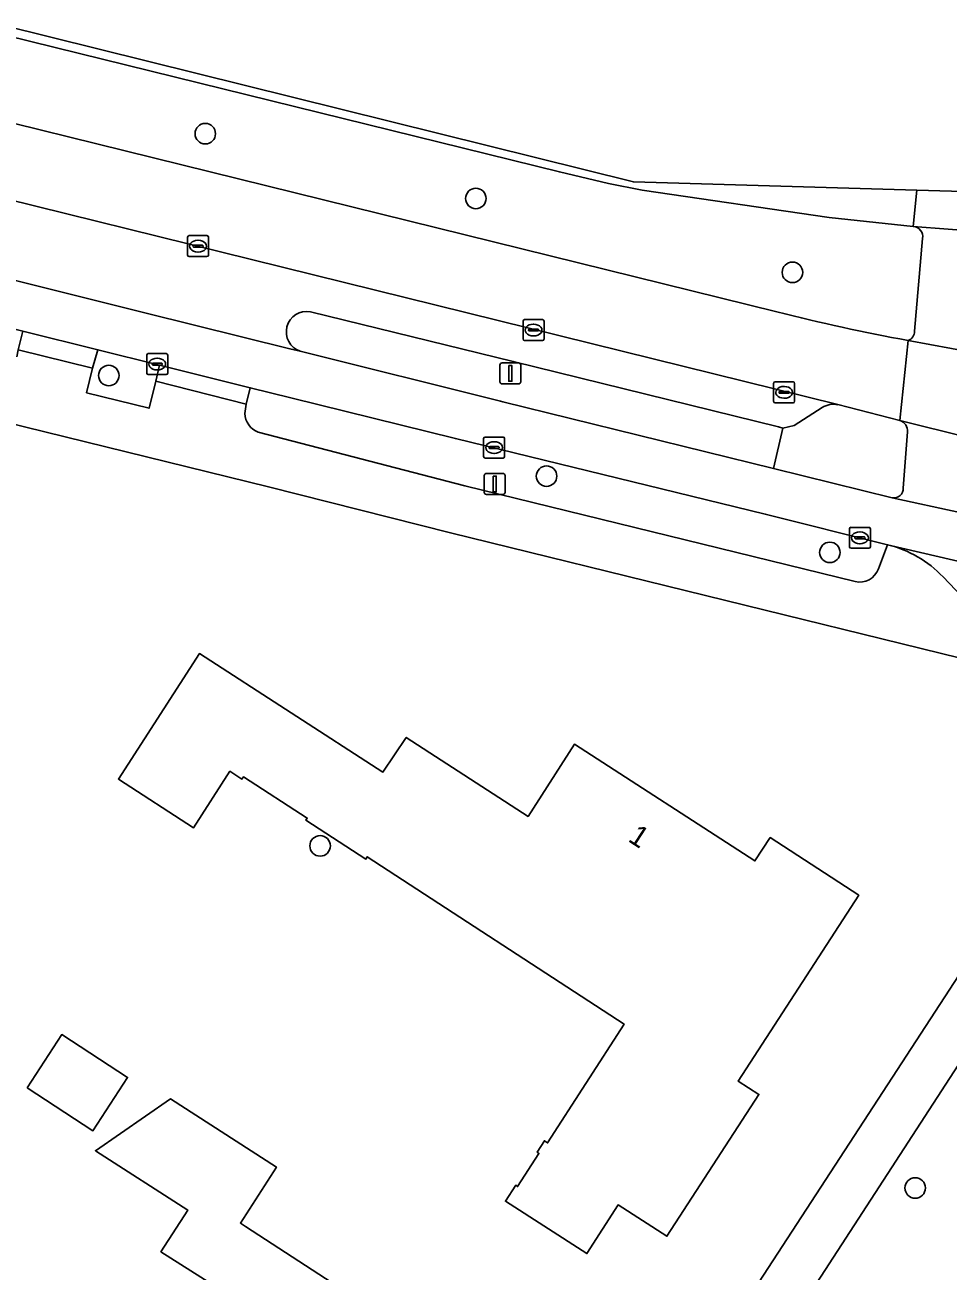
# Model space of a CAD drawing. Extents: x 161139 to 161601, y 381708 to 382245.
# Drawn here: x 161533 to 161577, y 382109.7 to 382169.1 of the extents above; entities that cross this region are included whole.
import ezdxf

# ---------------------------------------------------------------- set-up
doc = ezdxf.new("R2010")
doc.units = 0
for name, color, linetype in [('IMGEO_Berm_groen', 7, 'Continuous'), ('IMGEO_Boom', 7, 'Continuous'), ('IMGEO_Erf', 7, 'Continuous'), ('IMGEO_Fietspad_gesloten', 7, 'Continuous'), ('IMGEO_Groenvoorziening', 7, 'Continuous'), ('IMGEO_Kolk', 7, 'Continuous'), ('IMGEO_Lichtmast', 7, 'Continuous'), ('IMGEO_Pand', 7, 'Continuous'), ('IMGEO_Pand_nummerreeks', 7, 'Continuous'), ('IMGEO_Parkeervlak_open', 7, 'Continuous'), ('IMGEO_Rijbaan_lokaal_gesloten', 7, 'Continuous'), ('IMGEO_Voetpad_open', 7, 'Continuous')]:
    doc.layers.add(name, color=color, linetype=linetype)

msp = doc.modelspace()

# ---------------------------------------------------------------- linework, layer by layer
at = {"layer": 'IMGEO_Berm_groen'}
for points in [[(161500, 382176.547), (161460.894, 382186.197), (161420.058, 382196.306), (161417.456, 382196.964), (161416.542, 382193.184), (161418.72, 382192.635), (161459.898, 382182.379), (161500, 382172.465), (161568.862, 382155.44)], [(161575.364, 382159.517), (161571.347, 382159.936), (161562.428, 382161.253), (161560.838, 382161.565), (161558.491, 382162.113), (161500, 382176.547)], [(161575.423, 382154.516), (161575.807, 382158.946)], [(161556.292, 382153.08), (161546.612, 382155.453)], [(161546.127, 382153.566), (161555.682, 382151.185), (161555.792, 382151.158), (161568.691, 382147.976), (161569.142, 382149.901), (161568.93, 382149.958), (161556.292, 382153.08)], [(161553.532, 382149.4), (161545.675, 382151.345), (161543.747, 382151.827), (161543.551, 382151.041), (161543.482, 382150.599)], [(161571.016, 382150.879), (161569.692, 382150.02), (161569.142, 382149.901), (161568.691, 382147.976), (161574.358, 382146.578)], [(161574.719, 382150.267), (161571.771, 382151.019)], [(161544.121, 382149.704), (161553.984, 382147.153), (161572.587, 382142.588)], [(161574.88, 382147.043), (161575.088, 382149.718)], [(161573.699, 382143.186), (161574.138, 382144.342), (161568.305, 382145.8), (161553.532, 382149.4)]]:
    msp.add_lwpolyline(points, dxfattribs=at)
msp.add_lwpolyline([(161539.427, 382152.906), (161536.483, 382153.641), (161536.22, 382152.756), (161535.94, 382151.584), (161538.923, 382150.852), (161539.24, 382152.141)], close=True, dxfattribs=at)
for centre, radius, start, end in [((161575.324, 382159.028), 0.49, 350.32513, 85.28576), ((161546.444, 382154.49), 0.977, 80.08882, 251.08265), ((161592.831, 382250.474), 98.01, 255.84435, 259.58731), ((161574.946, 382154.523), 0.477, 290.99608, 359.1253), ((161571.568, 382150.009), 1.03, 78.61773, 122.3924), ((161544.511, 382150.658), 1.03, 183.27164, 247.77949), ((161574.574, 382149.771), 0.517, 354.12182, 73.69074), ((161574.442, 382147.009), 0.439, 258.97932, 4.41027), ((161572.81, 382143.505), 0.944, 256.31287, 340.22717)]:
    msp.add_arc(centre, radius, start, end, dxfattribs=at)
at = {"layer": 'IMGEO_Boom'}
for centre in [(161541.602, 382163.938), (161554.506, 382160.85), (161569.602, 382157.328), (161537.002, 382152.408), (161557.878, 382147.612), (161571.386, 382143.975), (161547.078, 382129.981), (161575.455, 382113.672)]:
    msp.add_circle(centre, 0.489, dxfattribs=at)
at = {"layer": 'IMGEO_Erf'}
for points in [[(161553.295, 382144.911), (161544.61, 382147.101), (161500, 382158.072), (161477.956, 382163.494), (161457.897, 382168.303), (161418.52, 382178.097), (161389.844, 382185.251), (161387.058, 382185.651), (161384.186, 382184.996), (161381.949, 382183.375), (161380.259, 382181.034), (161377.586, 382172.934), (161374.321, 382163.969), (161372.26, 382158.835), (161369.98, 382153.637), (161365.084, 382143.565), (161365.175, 382143.293), (161389.855, 382127.317), (161408.789, 382114.947), (161450.498, 382088.211), (161500, 382056.07), (161523.437, 382040.853), (161561.628, 382099.383), (161581.409, 382129.761)], [(161581.865, 382135.377), (161579.137, 382138.37), (161577.621, 382138.939), (161553.295, 382144.911)]]:
    msp.add_lwpolyline(points, dxfattribs=at)
for points in [[(161541.319, 382139.15), (161550.072, 382133.499), (161551.185, 382135.157), (161556.993, 382131.385), (161559.207, 382134.83), (161567.811, 382129.265), (161568.543, 382130.38), (161572.764, 382127.628), (161567.013, 382118.771), (161568.005, 382118.131), (161563.616, 382111.372), (161561.29, 382112.864), (161559.803, 382110.542), (161555.917, 382113.042), (161556.405, 382113.798), (161556.497, 382113.739), (161557.516, 382115.321), (161557.423, 382115.381), (161557.772, 382115.923), (161557.928, 382115.823), (161561.573, 382121.485), (161549.327, 382129.461), (161549.259, 382129.356), (161546.398, 382131.202), (161546.466, 382131.307), (161543.421, 382133.271), (161543.353, 382133.166), (161542.779, 382133.537), (161541.046, 382130.85), (161537.458, 382133.165)], [(161533.101, 382118.442), (161534.754, 382120.986), (161537.895, 382118.945), (161536.243, 382116.402)], [(161548.616, 382099.647), (161539.661, 382105.481), (161541.863, 382109.109), (161539.49, 382110.634), (161540.764, 382112.614), (161536.361, 382115.445), (161539.948, 382117.916), (161544.995, 382114.67), (161543.277, 382111.999), (161543.522, 382111.842), (161553.735, 382105.188), (161557.924, 382102.459), (161556.035, 382099.56), (161554.976, 382100.25), (161552.805, 382096.917)]]:
    msp.add_lwpolyline(points, close=True, dxfattribs=at)
at = {"layer": 'IMGEO_Fietspad_gesloten'}
for points in [[(161582.536, 382144.993), (161577.725, 382145.856), (161577.59, 382145.885), (161574.358, 382146.578), (161568.691, 382147.976), (161555.792, 382151.158), (161555.682, 382151.185), (161546.127, 382153.566), (161545.639, 382153.688), (161538.79, 382155.377), (161531.581, 382157.18), (161514.959, 382161.288), (161502.062, 382164.475), (161500, 382164.986), (161487.403, 382168.106)], [(161479.47, 382167.765), (161485.068, 382166.376), (161500, 382162.686), (161504.007, 382161.696), (161512.622, 382159.561), (161532.902, 382154.52), (161536.483, 382153.641), (161539.427, 382152.906), (161543.747, 382151.827), (161545.675, 382151.345), (161553.532, 382149.4), (161568.305, 382145.8), (161574.138, 382144.342), (161581.108, 382142.72), (161581.172, 382142.729), (161581.235, 382142.73), (161582.249, 382142.688), (161587.211, 382142.279), (161587.528, 382142.145), (161584.946, 382145.654)], [(161581.108, 382142.72), (161574.138, 382144.342)], [(161576.782, 382142.804), (161581.211, 382138.152), (161582.049, 382137.272), (161583.462, 382135.788), (161585.226, 382136.989), (161585.156, 382137.082), (161584.473, 382137.935), (161580.917, 382141.83)]]:
    msp.add_lwpolyline(points, dxfattribs=at)
msp.add_arc((161572.854, 382139.092), 5.405, 43.37531, 76.25204, dxfattribs=at)
at = {"layer": 'IMGEO_Groenvoorziening'}
msp.add_lwpolyline([(161579.832, 382114.053), (161581.47, 382118.537), (161583.268, 382124.041), (161581.267, 382125.334), (161568.38, 382105.476), (161573.086, 382102.543), (161573.302, 382103.064), (161575.329, 382102.253), (161576.98, 382106.377)], close=True, dxfattribs=at)
at = {"layer": 'IMGEO_Kolk'}
for p, q in [((161540.756, 382158.151), (161540.756, 382159.003)), ((161540.831, 382159.077), (161541.683, 382159.077)), ((161541.757, 382159.003), (161541.757, 382158.151)), ((161541.015, 382158.571), (161541.015, 382158.583)), ((161541.453, 382158.534), (161541.055, 382158.534)), ((161541.058, 382158.62), (161541.456, 382158.62)), ((161541.244, 382158.857), (161541.269, 382158.857)), ((161541.499, 382158.583), (161541.499, 382158.571)), ((161541.683, 382158.077), (161540.831, 382158.077)), ((161541.267, 382158.297), (161541.242, 382158.297)), ((161556.755, 382154.15), (161556.755, 382155.002)), ((161556.83, 382155.076), (161557.682, 382155.076)), ((161557.243, 382154.856), (161557.268, 382154.856)), ((161557.756, 382155.002), (161557.756, 382154.15)), ((161557.014, 382154.57), (161557.014, 382154.582)), ((161557.452, 382154.533), (161557.054, 382154.533)), ((161557.057, 382154.619), (161557.455, 382154.619)), ((161557.266, 382154.296), (161557.241, 382154.296)), ((161557.498, 382154.582), (161557.498, 382154.57)), ((161557.682, 382154.076), (161556.83, 382154.076)), ((161538.81, 382152.527), (161538.81, 382153.379)), ((161538.885, 382153.453), (161539.737, 382153.453)), ((161539.298, 382153.233), (161539.323, 382153.233)), ((161539.811, 382153.379), (161539.811, 382152.527)), ((161539.737, 382152.453), (161538.885, 382152.453)), ((161539.069, 382152.947), (161539.069, 382152.959)), ((161539.507, 382152.91), (161539.109, 382152.91)), ((161539.112, 382152.996), (161539.51, 382152.996)), ((161539.321, 382152.673), (161539.296, 382152.673)), ((161539.553, 382152.959), (161539.553, 382152.947)), ((161568.705, 382151.181), (161568.705, 382152.033)), ((161568.78, 382152.107), (161569.632, 382152.107)), ((161569.193, 382151.887), (161569.218, 382151.887)), ((161569.706, 382152.033), (161569.706, 382151.181)), ((161568.964, 382151.601), (161568.964, 382151.613)), ((161569.402, 382151.564), (161569.004, 382151.564)), ((161569.007, 382151.65), (161569.405, 382151.65)), ((161569.216, 382151.327), (161569.191, 382151.327)), ((161569.448, 382151.613), (161569.448, 382151.601)), ((161569.632, 382151.107), (161568.78, 382151.107)), ((161554.952, 382149.474), (161555.804, 382149.474)), ((161554.877, 382148.548), (161554.877, 382149.4)), ((161555.136, 382148.968), (161555.136, 382148.98)), ((161555.574, 382148.931), (161555.176, 382148.931)), ((161555.179, 382149.017), (161555.577, 382149.017)), ((161555.365, 382149.254), (161555.39, 382149.254)), ((161555.62, 382148.98), (161555.62, 382148.968)), ((161555.878, 382149.4), (161555.878, 382148.548)), ((161555.804, 382148.474), (161554.952, 382148.474)), ((161555.388, 382148.694), (161555.363, 382148.694)), ((161572.321, 382144.244), (161572.321, 382145.096)), ((161572.396, 382145.17), (161573.248, 382145.17)), ((161572.809, 382144.95), (161572.834, 382144.95)), ((161573.322, 382145.096), (161573.322, 382144.244)), ((161573.248, 382144.17), (161572.396, 382144.17)), ((161572.58, 382144.664), (161572.58, 382144.676)), ((161573.018, 382144.627), (161572.62, 382144.627)), ((161572.623, 382144.713), (161573.021, 382144.713)), ((161572.832, 382144.39), (161572.807, 382144.39)), ((161573.064, 382144.676), (161573.064, 382144.664))]:
    msp.add_line(p, q, dxfattribs=at)
for points in [[(161540.756, 382158.151), (161540.756, 382159.003)], [(161540.831, 382159.077), (161541.683, 382159.077)], [(161541.757, 382159.003), (161541.757, 382158.151)], [(161541.683, 382158.077), (161540.831, 382158.077)], [(161556.755, 382154.15), (161556.755, 382155.002)], [(161556.83, 382155.076), (161557.682, 382155.076)], [(161557.756, 382155.002), (161557.756, 382154.15)], [(161557.682, 382154.076), (161556.83, 382154.076)], [(161538.81, 382152.527), (161538.81, 382153.379)], [(161538.885, 382153.453), (161539.737, 382153.453)], [(161539.811, 382153.379), (161539.811, 382152.527)], [(161539.737, 382152.453), (161538.885, 382152.453)], [(161568.705, 382151.181), (161568.705, 382152.033)], [(161568.78, 382152.107), (161569.632, 382152.107)], [(161569.706, 382152.033), (161569.706, 382151.181)], [(161569.632, 382151.107), (161568.78, 382151.107)], [(161554.952, 382149.474), (161555.804, 382149.474)], [(161554.877, 382148.548), (161554.877, 382149.4)], [(161555.878, 382149.4), (161555.878, 382148.548)], [(161555.804, 382148.474), (161554.952, 382148.474)], [(161572.321, 382144.244), (161572.321, 382145.096)], [(161572.396, 382145.17), (161573.248, 382145.17)], [(161573.322, 382145.096), (161573.322, 382144.244)], [(161573.248, 382144.17), (161572.396, 382144.17)]]:
    msp.add_lwpolyline(points, dxfattribs=at)
for centre, radius, start, end in [((161540.833, 382159.001), 0.0765, 91.55205, 178.44795), ((161540.833, 382159.001), 0.0765, 91.55205, 178.44795), ((161541.681, 382159.001), 0.0765, 1.55205, 88.44795), ((161541.681, 382159.001), 0.0765, 1.55205, 88.44795), ((161541.055, 382158.58), 0.0403, 85.87752, 175.75265), ((161541.052, 382158.57), 0.0366, 178.93798, 274.71019), ((161541.456, 382158.577), 0.043, 264.86636, 352.45326), ((161541.46, 382158.582), 0.0386, 1.73085, 96.63898), ((161540.833, 382158.153), 0.0765, 181.55205, 268.44795), ((161540.833, 382158.153), 0.0765, 181.55205, 268.44795), ((161541.681, 382158.153), 0.0765, 271.55205, 358.44795), ((161541.681, 382158.153), 0.0765, 271.55205, 358.44795), ((161556.832, 382155), 0.0765, 91.55205, 178.44795), ((161556.832, 382155), 0.0765, 91.55205, 178.44795), ((161557.68, 382155), 0.0765, 1.55205, 88.44795), ((161557.68, 382155), 0.0765, 1.55205, 88.44795), ((161557.054, 382154.579), 0.0403, 85.87752, 175.75265), ((161557.051, 382154.569), 0.0366, 178.93798, 274.71019), ((161557.455, 382154.576), 0.043, 264.86636, 352.45326), ((161557.459, 382154.581), 0.0386, 1.73085, 96.63898), ((161556.832, 382154.152), 0.0765, 181.55205, 268.44795), ((161556.832, 382154.152), 0.0765, 181.55205, 268.44795), ((161557.68, 382154.152), 0.0765, 271.55205, 358.44795), ((161557.68, 382154.152), 0.0765, 271.55205, 358.44795), ((161538.887, 382153.377), 0.0765, 91.55205, 178.44795), ((161538.887, 382153.377), 0.0765, 91.55205, 178.44795), ((161539.735, 382153.377), 0.0765, 1.55205, 88.44795), ((161539.735, 382153.377), 0.0765, 1.55205, 88.44795), ((161538.887, 382152.529), 0.0765, 181.55205, 268.44795), ((161538.887, 382152.529), 0.0765, 181.55205, 268.44795), ((161539.109, 382152.956), 0.0403, 85.87752, 175.75265), ((161539.106, 382152.946), 0.0366, 178.93798, 274.71019), ((161539.51, 382152.953), 0.043, 264.86636, 352.45326), ((161539.514, 382152.958), 0.0386, 1.73085, 96.63898), ((161539.735, 382152.529), 0.0765, 271.55205, 358.44795), ((161539.735, 382152.529), 0.0765, 271.55205, 358.44795), ((161568.782, 382152.031), 0.0765, 91.55205, 178.44795), ((161568.782, 382152.031), 0.0765, 91.55205, 178.44795), ((161569.63, 382152.031), 0.0765, 1.55205, 88.44795), ((161569.63, 382152.031), 0.0765, 1.55205, 88.44795), ((161569.004, 382151.61), 0.0403, 85.87752, 175.75265), ((161569.001, 382151.6), 0.0366, 178.93798, 274.71019), ((161569.405, 382151.607), 0.043, 264.86636, 352.45326), ((161569.409, 382151.612), 0.0386, 1.73085, 96.63898), ((161568.782, 382151.183), 0.0765, 181.55205, 268.44795), ((161568.782, 382151.183), 0.0765, 181.55205, 268.44795), ((161569.63, 382151.183), 0.0765, 271.55205, 358.44795), ((161569.63, 382151.183), 0.0765, 271.55205, 358.44795), ((161554.954, 382149.398), 0.0765, 91.55205, 178.44795), ((161554.954, 382149.398), 0.0765, 91.55205, 178.44795), ((161555.802, 382149.398), 0.0765, 1.55205, 88.44795), ((161555.802, 382149.398), 0.0765, 1.55205, 88.44795), ((161555.176, 382148.977), 0.0403, 85.87752, 175.75265), ((161555.173, 382148.967), 0.0366, 178.93798, 274.71019), ((161555.577, 382148.974), 0.043, 264.86636, 352.45326), ((161555.581, 382148.979), 0.0386, 1.73085, 96.63898), ((161554.954, 382148.55), 0.0765, 181.55205, 268.44795), ((161554.954, 382148.55), 0.0765, 181.55205, 268.44795), ((161555.802, 382148.55), 0.0765, 271.55205, 358.44795), ((161555.802, 382148.55), 0.0765, 271.55205, 358.44795), ((161572.398, 382145.094), 0.0765, 91.55205, 178.44795), ((161572.398, 382145.094), 0.0765, 91.55205, 178.44795), ((161573.246, 382145.094), 0.0765, 1.55205, 88.44795), ((161573.246, 382145.094), 0.0765, 1.55205, 88.44795), ((161572.398, 382144.246), 0.0765, 181.55205, 268.44795), ((161572.398, 382144.246), 0.0765, 181.55205, 268.44795), ((161572.62, 382144.673), 0.0403, 85.87752, 175.75265), ((161572.617, 382144.663), 0.0366, 178.93798, 274.71019), ((161573.021, 382144.67), 0.043, 264.86636, 352.45326), ((161573.025, 382144.675), 0.0386, 1.73085, 96.63898), ((161573.246, 382144.246), 0.0765, 271.55205, 358.44795), ((161573.246, 382144.246), 0.0765, 271.55205, 358.44795)]:
    msp.add_arc(centre, radius, start, end, dxfattribs=at)
for centre, major_axis, ratio, start_param, end_param in [((161541.243, 382158.577), (-0.387, 0.002), 0.722429, 4.712389, 7.853982), ((161541.268, 382158.577), (-0.39, 0.002), 0.717154, 1.570796, 4.712389), ((161557.242, 382154.576), (-0.387, 0.002), 0.722429, 4.712389, 7.853982), ((161557.267, 382154.576), (-0.39, 0.002), 0.717154, 1.570796, 4.712389), ((161539.297, 382152.953), (-0.387, 0.002), 0.722429, 4.712389, 7.853982), ((161539.322, 382152.953), (-0.39, 0.002), 0.717154, 1.570796, 4.712389), ((161569.192, 382151.607), (-0.387, 0.002), 0.722429, 4.712389, 7.853982), ((161569.217, 382151.607), (-0.39, 0.002), 0.717154, 1.570796, 4.712389), ((161555.364, 382148.974), (-0.387, 0.002), 0.722429, 4.712389, 7.853982), ((161555.389, 382148.974), (-0.39, 0.002), 0.717154, 1.570796, 4.712389), ((161572.808, 382144.67), (-0.387, 0.002), 0.722429, 4.712389, 7.853982), ((161572.833, 382144.67), (-0.39, 0.002), 0.717154, 1.570796, 4.712389)]:
    msp.add_ellipse(centre, major_axis=major_axis, ratio=ratio, start_param=start_param, end_param=end_param, dxfattribs=at)
at = {"layer": 'IMGEO_Lichtmast'}
for p, q in [((161555.654, 382152.109), (161555.654, 382152.909)), ((161555.654, 382152.909), (161555.654, 382152.109)), ((161555.754, 382153.009), (161556.544, 382153.009)), ((161556.544, 382153.009), (161555.754, 382153.009)), ((161556.644, 382152.909), (161556.644, 382152.109)), ((161556.644, 382152.109), (161556.644, 382152.909)), ((161556.544, 382152.009), (161555.754, 382152.009)), ((161555.754, 382152.009), (161556.544, 382152.009)), ((161555.006, 382147.737), (161555.796, 382147.737)), ((161555.796, 382147.737), (161555.006, 382147.737)), ((161554.906, 382146.837), (161554.906, 382147.637)), ((161554.906, 382147.637), (161554.906, 382146.837)), ((161555.896, 382147.637), (161555.896, 382146.837)), ((161555.896, 382146.837), (161555.896, 382147.637)), ((161555.796, 382146.737), (161555.006, 382146.737)), ((161555.006, 382146.737), (161555.796, 382146.737))]:
    msp.add_line(p, q, dxfattribs=at)
for points in [[(161556.074, 382152.884), (161556.224, 382152.884), (161556.224, 382152.134), (161556.074, 382152.134), (161556.074, 382152.884)], [(161555.326, 382147.612), (161555.476, 382147.612), (161555.476, 382146.862), (161555.326, 382146.862), (161555.326, 382147.612)]]:
    msp.add_lwpolyline(points, dxfattribs=at)
for centre, start, end in [((161555.754, 382152.909), 90, 180), ((161555.754, 382152.909), 90, 180), ((161556.544, 382152.909), 0, 90), ((161556.544, 382152.909), 360, 90), ((161555.754, 382152.109), 180, 270), ((161555.754, 382152.109), 180, 270), ((161556.544, 382152.109), 270, 0), ((161556.544, 382152.109), 270, 0), ((161555.006, 382147.637), 90, 180), ((161555.006, 382147.637), 90, 180), ((161555.796, 382147.637), 0, 90), ((161555.796, 382147.637), 360, 90), ((161555.006, 382146.837), 180, 270), ((161555.006, 382146.837), 180, 270), ((161555.796, 382146.837), 270, 0), ((161555.796, 382146.837), 270, 0)]:
    msp.add_arc(centre, 0.1, start, end, dxfattribs=at)
at = {"layer": 'IMGEO_Pand'}
for points in [[(161550.072, 382133.499), (161541.319, 382139.15), (161537.458, 382133.165), (161541.046, 382130.85), (161542.779, 382133.537), (161543.353, 382133.166), (161543.421, 382133.271), (161546.466, 382131.307), (161546.398, 382131.202), (161549.259, 382129.356), (161549.327, 382129.461), (161561.573, 382121.485), (161557.928, 382115.823), (161557.772, 382115.923), (161557.423, 382115.381), (161557.516, 382115.321), (161556.497, 382113.739), (161556.405, 382113.798), (161555.917, 382113.042), (161559.803, 382110.542), (161561.29, 382112.864), (161563.616, 382111.372), (161568.005, 382118.131), (161567.013, 382118.771), (161572.764, 382127.628), (161568.543, 382130.38), (161567.811, 382129.265), (161559.207, 382134.83), (161556.993, 382131.385), (161551.185, 382135.157)], [(161533.101, 382118.442), (161536.243, 382116.402), (161537.895, 382118.945), (161534.754, 382120.986)], [(161548.616, 382099.647), (161552.805, 382096.917), (161554.976, 382100.25), (161556.035, 382099.56), (161557.924, 382102.459), (161553.735, 382105.188), (161543.522, 382111.842), (161543.277, 382111.999), (161544.995, 382114.67), (161539.948, 382117.916), (161536.361, 382115.445), (161540.764, 382112.614), (161539.49, 382110.634), (161541.863, 382109.109), (161539.661, 382105.481)]]:
    msp.add_lwpolyline(points, close=True, dxfattribs=at)
at = {"layer": 'IMGEO_Parkeervlak_open'}
for points in [[(161571.771, 382151.019), (161502.587, 382168.125)], [(161531.581, 382157.18), (161538.79, 382155.377), (161545.639, 382153.688), (161546.127, 382153.566)], [(161546.612, 382155.453), (161556.292, 382153.08), (161568.93, 382149.958), (161569.142, 382149.901), (161569.692, 382150.02), (161571.016, 382150.879)]]:
    msp.add_lwpolyline(points, dxfattribs=at)
for centre, radius, start, end in [((161546.444, 382154.49), 0.977, 80.08882, 251.08265), ((161571.568, 382150.009), 1.03, 78.61773, 122.3924)]:
    msp.add_arc(centre, radius, start, end, dxfattribs=at)
at = {"layer": 'IMGEO_Rijbaan_lokaal_gesloten'}
for points in [[(161371.295, 382209.7), (161379.73, 382204.16), (161385.013, 382201.164), (161389.691, 382198.806), (161397.081, 382195.854), (161402.036, 382194.12), (161402.198, 382194.055), (161405.248, 382192.835), (161406.546, 382192.371), (161409.616, 382191.449), (161412.637, 382190.575), (161412.768, 382190.537), (161412.878, 382190.505), (161415.442, 382189.785), (161420.449, 382188.487), (161459.102, 382178.908), (161500, 382168.766), (161502.587, 382168.125), (161571.771, 382151.019), (161574.719, 382150.267), (161575.117, 382154.078)], [(161575.538, 382161.247), (161562.018, 382161.64), (161415.973, 382197.911)], [(161568.862, 382155.44), (161500, 382172.465), (161459.898, 382182.379), (161418.72, 382192.635), (161416.542, 382193.184)], [(161460.894, 382186.197), (161500, 382176.547), (161558.491, 382162.113), (161560.838, 382161.565), (161562.428, 382161.253), (161571.347, 382159.936), (161575.364, 382159.517), (161575.538, 382161.247)], [(161600.631, 382159.85), (161600.82, 382160.511), (161575.538, 382161.247), (161575.364, 382159.517), (161578.698, 382159.266), (161582.161, 382159.046), (161586.144, 382158.862), (161589.173, 382158.758), (161600.631, 382159.85), (161600.631, 382159.85)], [(161584.529, 382152.691), (161581.689, 382153.028), (161581.522, 382153.051), (161578.323, 382153.496), (161578.216, 382153.513), (161575.117, 382154.078), (161574.719, 382150.267), (161577.978, 382149.452), (161578.219, 382149.38), (161579.826, 382148.903), (161581.592, 382148.301), (161583.013, 382147.446), (161584.296, 382146.447), (161584.666, 382146.035), (161584.946, 382145.654), (161596.564, 382145.611)]]:
    msp.add_lwpolyline(points, dxfattribs=at)
msp.add_arc((161592.831, 382250.474), 98.01, 255.84435, 259.58731, dxfattribs=at)
at = {"layer": 'IMGEO_Voetpad_open'}
for points in [[(161378.971, 382187.245), (161387.058, 382185.651), (161389.844, 382185.251), (161418.52, 382178.097), (161457.897, 382168.303), (161477.956, 382163.494), (161500, 382158.072), (161544.61, 382147.101), (161553.295, 382144.911), (161577.621, 382138.939), (161579.137, 382138.37), (161582.049, 382137.272), (161581.211, 382138.152), (161576.782, 382142.804)], [(161578.698, 382159.266), (161575.364, 382159.517)], [(161575.807, 382158.946), (161575.423, 382154.516)], [(161543.482, 382150.599), (161543.551, 382151.041), (161539.24, 382152.141), (161538.923, 382150.852), (161535.94, 382151.584), (161536.22, 382152.756), (161532.682, 382153.637), (161532.619, 382153.305)], [(161575.117, 382154.078), (161578.216, 382153.513)], [(161577.978, 382149.452), (161574.719, 382150.267)], [(161572.587, 382142.588), (161553.984, 382147.153), (161544.121, 382149.704)], [(161575.088, 382149.718), (161574.88, 382147.043)], [(161574.358, 382146.578), (161577.59, 382145.885)], [(161574.138, 382144.342), (161573.699, 382143.186)], [(161581.409, 382129.761), (161561.628, 382099.383), (161523.437, 382040.853), (161525.518, 382039.495), (161528.456, 382043.995), (161532.291, 382049.829), (161533.813, 382052.367), (161540.355, 382062.295), (161541.805, 382064.505), (161548.238, 382074.428), (161549.678, 382076.751), (161556.061, 382086.613), (161557.579, 382088.971), (161563.831, 382098.367), (161565.463, 382100.982), (161566.592, 382102.722), (161568.38, 382105.476), (161581.267, 382125.334)]]:
    msp.add_lwpolyline(points, dxfattribs=at)
for points in [[(161532.682, 382153.637), (161536.22, 382152.756), (161536.483, 382153.641), (161532.902, 382154.52)], [(161539.427, 382152.906), (161539.24, 382152.141), (161543.551, 382151.041), (161543.747, 382151.827)]]:
    msp.add_lwpolyline(points, close=True, dxfattribs=at)
for centre, radius, start, end in [((161575.324, 382159.028), 0.49, 350.32513, 85.28576), ((161574.946, 382154.523), 0.477, 290.99608, 359.1253), ((161544.511, 382150.658), 1.03, 183.27164, 247.77949), ((161574.574, 382149.771), 0.517, 354.12182, 73.69074), ((161574.442, 382147.009), 0.439, 258.97932, 4.41027), ((161572.854, 382139.092), 5.405, 43.37531, 76.25204), ((161572.81, 382143.505), 0.944, 256.31287, 340.22717)]:
    msp.add_arc(centre, radius, start, end, dxfattribs=at)

# ---------------------------------------------------------------- texts
at = {"layer": 'IMGEO_Pand_nummerreeks'}
msp.add_text('1', height=1, rotation=326.90596, dxfattribs=at).set_placement((161561.715, 382130.232))

doc.saveas('drawing.dxf')
